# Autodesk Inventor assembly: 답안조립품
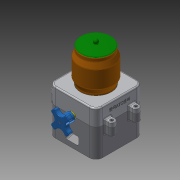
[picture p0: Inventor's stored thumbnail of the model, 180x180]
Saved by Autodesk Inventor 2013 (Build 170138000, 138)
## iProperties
Created: 2018-01
Part Number: 답안조립품
Document SubType Name: Assembly
Designer: Administrator
Author: Administrator
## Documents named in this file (9)
- C:\Users\Administrator\Desktop\480108V1012\답안조립품.iam
- C:\Users\Administrator\Desktop\480108V1012\본체.ipt
- C:\Users\Administrator\Desktop\480108V1012\핸들축.ipt
- C:\Users\Administrator\Desktop\480108V1012\핸들.ipt
- C:\Users\Administrator\Desktop\480108V1012\볼트 M3x12.ipt
- C:\Users\Administrator\Desktop\480108V1012\용기.ipt
- C:\Users\Administrator\Desktop\480108V1012\용기캡.ipt
- C:\Users\Administrator\Desktop\480108V1012\본체커버.ipt
- C:\Users\Administrator\Desktop\480108V1012\볼트 M4x12.ipt
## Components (2 placed, 2 different names)
1. 핸들축:1
2. 핸들:1
